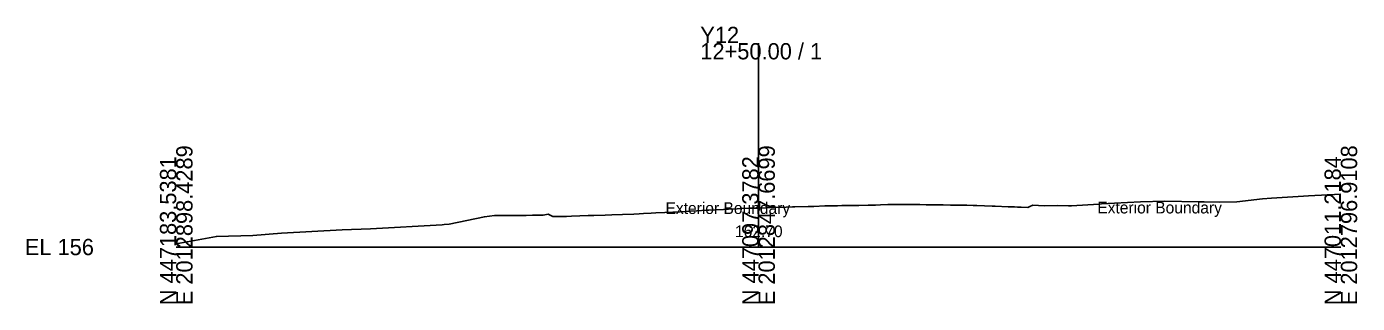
# Model space of a CAD drawing. Extents: x -26 to 1203, y -10 to 9542.
# Drawn here: x -25.7 to 202.8, y 4990.3 to 5037.9 of the extents above; entities that cross this region are included whole.
import ezdxf

# ---------------------------------------------------------------- set-up
doc = ezdxf.new("R2010")
doc.units = 0
for name, color, linetype in [('Default', 7, 'Continuous'), ('Exist Cross Section Cell', 7, 'Continuous'), ('Exist XS Center Line Elevation Label', 7, 'Continuous'), ('Exist XS Ground Line', 7, 'Continuous'), ('Prop CMT Pvmt Course 1', 7, 'Continuous'), ('Scratch_Level_0', 7, 'Continuous')]:
    doc.layers.add(name, color=color, linetype=linetype)

msp = doc.modelspace()

# ---------------------------------------------------------------- linework, layer by layer
at = {"layer": 'Exist Cross Section Cell'}
for p, q in [((100, 5000), (100, 5035.05)), ((0, 5000), (100, 5000)), ((100, 5000), (200, 5000))]:
    msp.add_line(p, q, dxfattribs=at)
at = {"layer": 'Exist XS Ground Line'}
msp.add_lwpolyline([(0, 5000.57), (6.89, 5001.81), (13.14, 5001.99), (18.09, 5002.36), (28.47, 5002.94), (33.37, 5003.15), (45.67, 5003.82), (46.03, 5003.86), (46.85, 5003.9), (52.92, 5005.21), (54.64, 5005.43), (57.17, 5005.41), (57.65, 5005.43), (60.12, 5005.43), (61.16, 5005.5), (62.99, 5005.5), (63.89, 5005.66), (64.66, 5005.24), (65.32, 5005.24), (67.03, 5005.26), (67.86, 5005.31), (69.31, 5005.36), (70.76, 5005.4), (71.73, 5005.43), (73.67, 5005.5), (74.78, 5005.54), (76.65, 5005.59), (78.61, 5005.65), (79.48, 5005.7), (80.27, 5005.74), (81.56, 5005.82), (82.39, 5005.86), (83.93, 5005.95), (85.3, 5006.01), (86.53, 5006.07), (88.18, 5006.16), (89.39, 5006.23), (91.07, 5006.31), (91.45, 5006.33), (93.96, 5006.45), (94.85, 5006.49), (96.31, 5006.57), (96.86, 5006.6), (98.48, 5006.67), (100, 5006.7), (101.31, 5006.74), (102.18, 5006.77), (102.69, 5006.78), (104.72, 5006.84), (105.83, 5006.88), (106.22, 5006.89), (108.5, 5006.95), (109.48, 5006.98), (111.4, 5007.06), (112.4, 5007.08), (113.56, 5007.09), (114.32, 5007.11), (116.07, 5007.14), (117.2, 5007.16), (118.82, 5007.2), (120.09, 5007.22), (120.97, 5007.24), (122.23, 5007.28), (122.97, 5007.29), (124.06, 5007.3), (125.9, 5007.29), (127.72, 5007.28), (128.8, 5007.27), (130.84, 5007.25), (131.38, 5007.24), (131.7, 5007.24), (132.97, 5007.22), (134.62, 5007.2), (135.03, 5007.19), (135.78, 5007.17), (136.88, 5007.15), (137.51, 5007.13), (140.14, 5007.04), (140.66, 5007.03), (142.85, 5006.93), (143.95, 5006.88), (144.45, 5006.86), (145.1, 5006.85), (146.23, 5006.81), (146.57, 5006.97), (147.1, 5007.21), (149.04, 5007.1), (151.26, 5007.13), (153.25, 5007.09), (153.76, 5007.09), (158.42, 5007.37), (158.87, 5007.4), (165.59, 5007.77), (169.78, 5007.86), (175.55, 5007.74), (176.51, 5007.79), (179.15, 5007.73), (182.14, 5007.79), (186.53, 5008.28), (188.11, 5008.39), (193.6, 5008.75), (194.43, 5008.81), (200, 5009.11)], dxfattribs=at)
at = {"layer": 'Prop CMT Pvmt Course 1'}
msp.add_lwpolyline([(85.79, 5006.04), (85.79, 5006.04)], dxfattribs=at)

# ---------------------------------------------------------------- texts
at = {"layer": 'Default'}
msp.add_text('-', height=0.0001, dxfattribs=at).set_placement((0, 5000))
at = {"layer": 'Exist Cross Section Cell'}
for s, p in [('Y12', (90, 5035.05)), ('12+50.00 / 1', (90, 5032.25)), ('EL 156', (-26, 4998.6))]:
    msp.add_text(s, height=2.8, dxfattribs=at).set_placement(p)
for s, p in [('E 2012898.4289', (2.8, 4990)), ('E 2012847.6699', (102.8, 4990)), ('E 2012796.9108', (202.8, 4990)), ('N 447183.5381', (0, 4990)), ('N 447097.3782', (100, 4990)), ('N 447011.2184', (200, 4990))]:
    msp.add_text(s, height=2.8, rotation=90, dxfattribs=at).set_placement(p)
at = {"layer": 'Exist XS Center Line Elevation Label'}
msp.add_text('162.70', height=2, dxfattribs=at).set_placement((95.95, 5001.7))
at = {"layer": 'Scratch_Level_0'}
for p in [(84.02, 5005.68), (158.17, 5005.77)]:
    msp.add_text('Exterior Boundary', height=2, dxfattribs=at).set_placement(p)

doc.saveas('drawing.dxf')
